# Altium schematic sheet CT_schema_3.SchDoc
size 322 x 302 mm
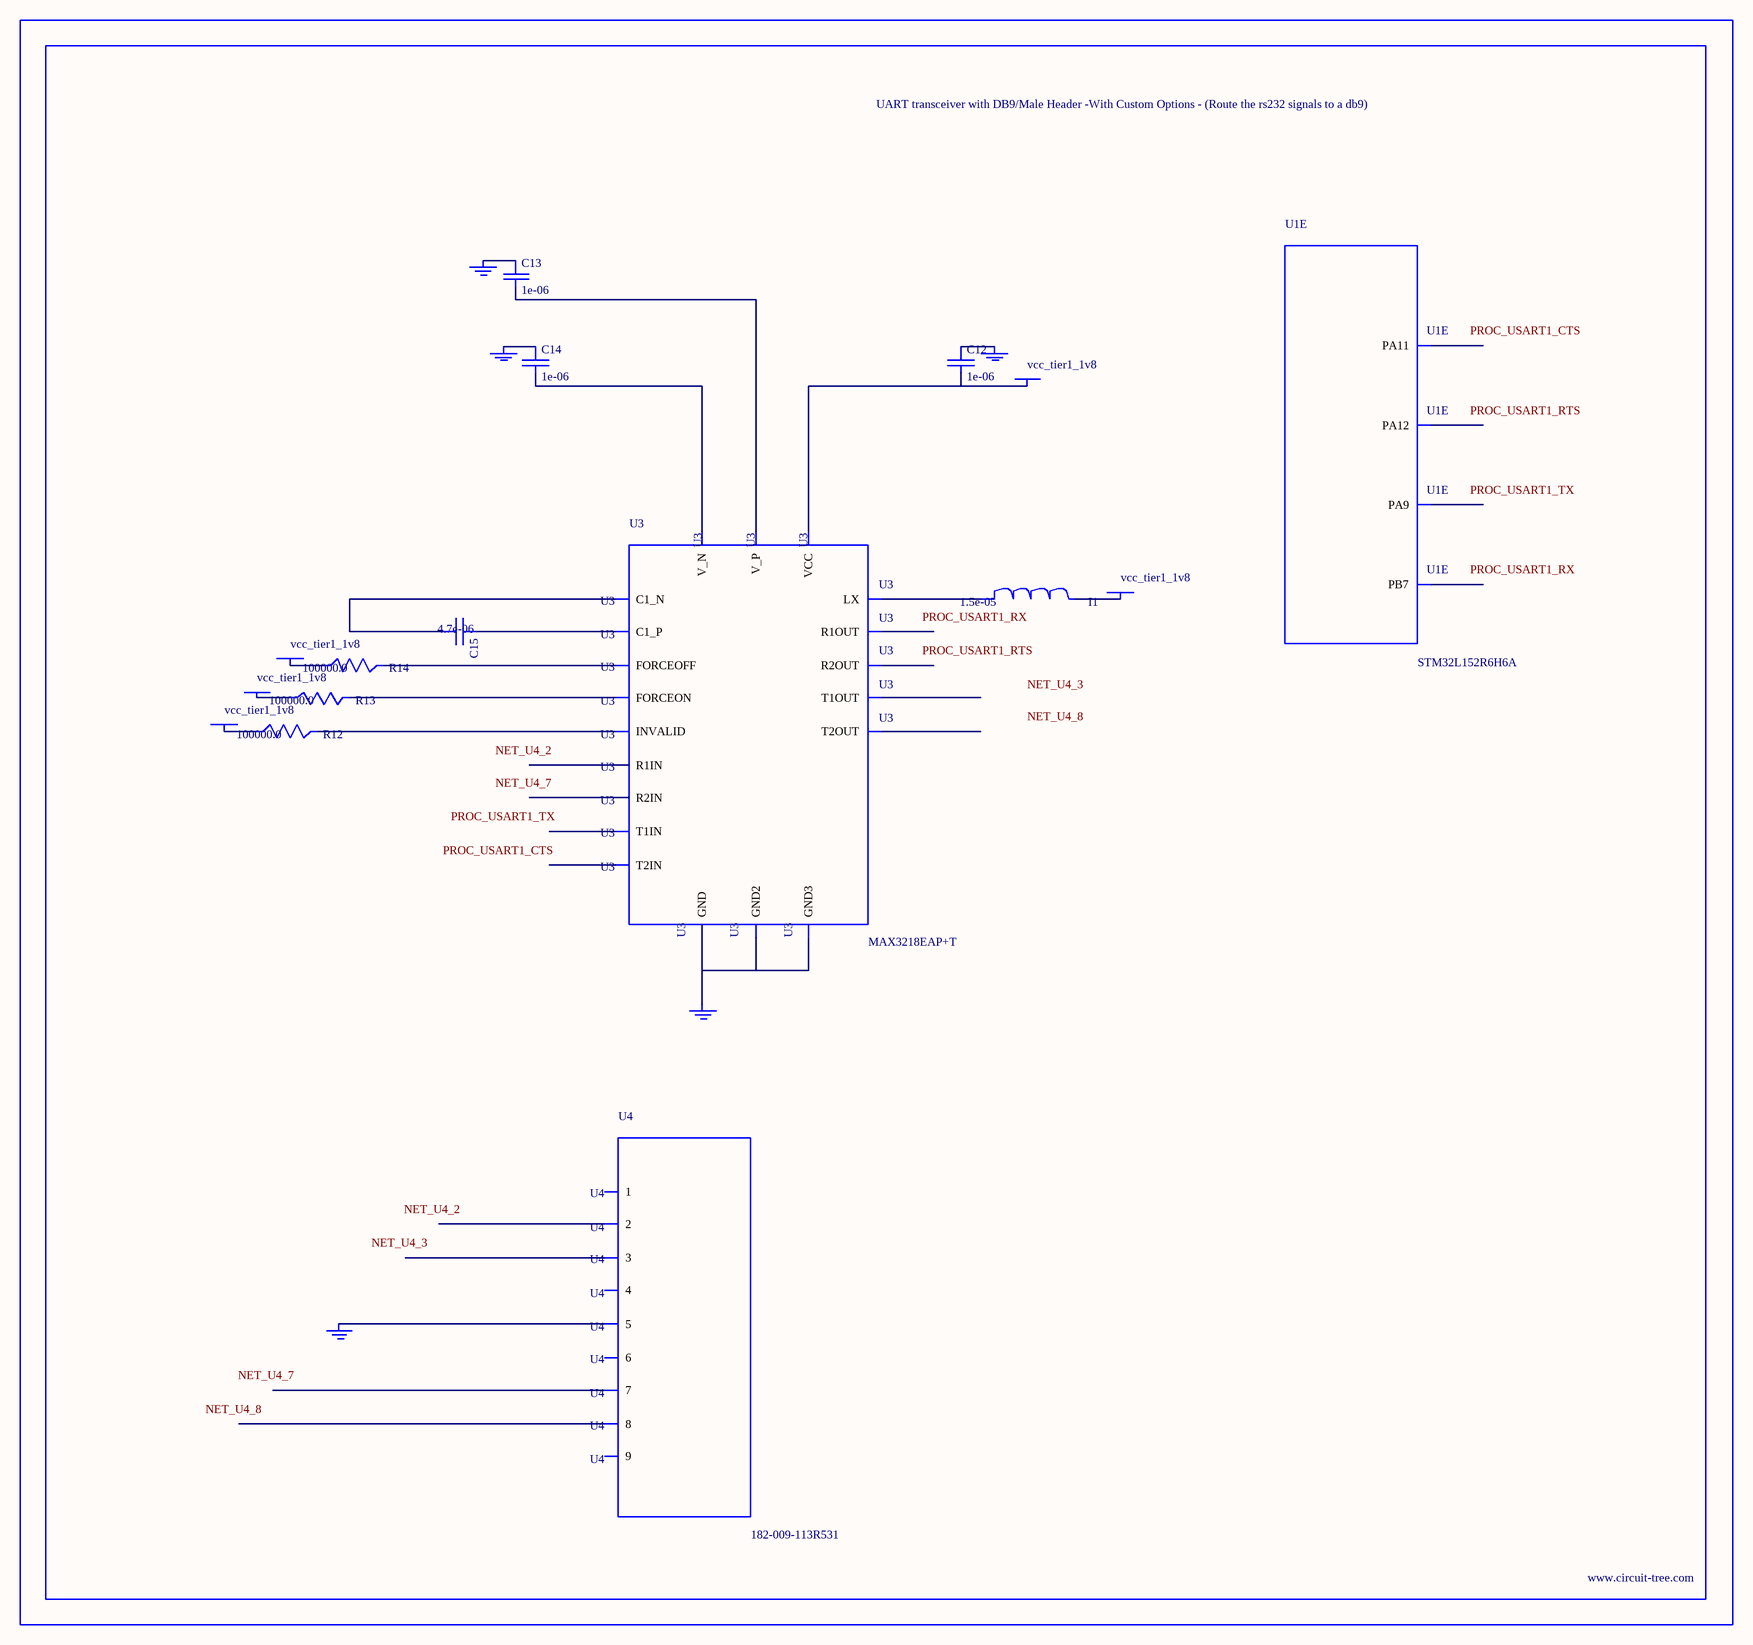
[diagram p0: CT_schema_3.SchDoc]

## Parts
BORDER2  (no value)
C12  1e-06  [C0603]
C13  1e-06  [C0603]
C14  1e-06  [C0603]
C15  4.7e-06  [C0805]
GND_INSTANCE_2_0  (no value)
GND_INSTANCE_2_1  (no value)
GND_INSTANCE_2_2  (no value)
GND_INSTANCE_2_3  (no value)
GND_INSTANCE_2_4  (no value)
I1  1.5e-05  [L1210]
POWER_INSTANCE_2_0  vcc_tier1_1v8
POWER_INSTANCE_2_1  vcc_tier1_1v8
POWER_INSTANCE_2_2  vcc_tier1_1v8
POWER_INSTANCE_2_3  vcc_tier1_1v8
POWER_INSTANCE_2_4  vcc_tier1_1v8
R12  100000.0  [R0603]
R13  100000.0  [R0603]
R14  100000.0  [R0603]
U1  STM32L152R6H6A  [TFBGA64]  (part E of 7)
U3  MAX3218EAP+T  [SSOP-20]
U4  182-009-113R531  [182-009-MALE]

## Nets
NetC12_1: C12.1 GND_INSTANCE_2_0.0(GND)
NetC12_2: C12.2 POWER_INSTANCE_2_4.0(PWR) U3.6(VCC)
NetC13_1: C13.1 GND_INSTANCE_2_2.0(GND)
NetC13_2: C13.2 U3.19(V_P)
NetC14_1: C14.1 GND_INSTANCE_2_1.0(GND)
NetC14_2: C14.2 U3.15(V_N)
NetC15_1: C15.1 U3.18(C1_P)
NetC15_2: C15.2 U3.16(C1_N)
NetGND_INSTANCE_2_3_0: GND_INSTANCE_2_3.0(GND) U3.5(GND) U3.17(GND2) U3.20(GND3)
NetGND_INSTANCE_2_4_0: GND_INSTANCE_2_4.0(GND) U4.5
NetI1_1: I1.1 U3.1(LX)
NetI1_2: I1.2 POWER_INSTANCE_2_0.0(PWR)
NetPOWER_INSTANCE_2_1_0: POWER_INSTANCE_2_1.0(PWR) R12.1
NetPOWER_INSTANCE_2_2_0: POWER_INSTANCE_2_2.0(PWR) R13.1
NetPOWER_INSTANCE_2_3_0: POWER_INSTANCE_2_3.0(PWR) R14.1
NetR12_2: R12.2 U3.2(INVALID)
NetR13_2: R13.2 U3.3(FORCEON)
NetR14_2: R14.2 U3.4(FORCEOFF)

Not connected (* = marked no-connect by the designer): U1 B8(PA12) C3(PB7) C7(PA9) C8(PA11); U3 7(T1IN) 8(T2IN) 9(R1OUT) 10(R2OUT) 11(R2IN) 12(R1IN) 13(T2OUT) 14(T1OUT); U4 1 2 3 4 6 7 8 9

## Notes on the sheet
- Labels drawn without touching a wire or pin: NET_U4_2, NET_U4_3, NET_U4_7, NET_U4_8, PROC_USART1_CTS, PROC_USART1_RTS, PROC_USART1_RX, PROC_USART1_TX

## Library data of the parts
BORDER2 = BORDER_PAGE2
C12-C14 = C0603C105K3RACTU
C15 = C0805C475K4RACTU
GND_INSTANCE_2_0-GND_INSTANCE_2_4 = GND
I1 = L1210R150MDWIT
POWER_INSTANCE_2_0-POWER_INSTANCE_2_4 = PWR
R12-R14 = RC0603JR-07100KL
